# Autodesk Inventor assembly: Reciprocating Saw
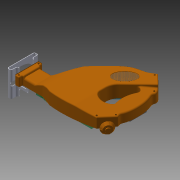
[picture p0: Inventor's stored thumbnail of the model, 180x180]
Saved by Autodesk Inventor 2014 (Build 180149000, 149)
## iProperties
Created: 2008-06
Part Number: Reciprocating Saw
Document SubType Name: Assembly
Designer: tangg
Mass: 711.371 g
Surface Area: 3987.93 cm^2
Volume: 242.811 cm^3
Density: 2.92973 g/cm^3
Author: tangg
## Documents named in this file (11)
- C:\Users\iTools\Desktop\tutorial files\Dynamic Simulation 1 and 2\Reciprocating Saw.iam
- C:\Users\iTools\Desktop\tutorial files\Dynamic Simulation 1 and 2\Saw layout.ipt
- C:\Users\iTools\Desktop\tutorial files\Dynamic Simulation 1 and 2\Guide.ipt
- C:\Users\iTools\Desktop\tutorial files\Dynamic Simulation 1 and 2\Motor housing.ipt
- C:\Users\iTools\Desktop\tutorial files\Dynamic Simulation 1 and 2\Case.ipt
- C:\Users\iTools\Desktop\tutorial files\Dynamic Simulation 1 and 2\Follower.ipt
- C:\Users\iTools\Desktop\tutorial files\Dynamic Simulation 1 and 2\Fence.ipt
- C:\Users\iTools\Desktop\tutorial files\Dynamic Simulation 1 and 2\Cam crank.iam
- C:\Users\iTools\Desktop\tutorial files\Dynamic Simulation 1 and 2\Motor.iam
- C:\Users\iTools\Desktop\tutorial files\Dynamic Simulation 1 and 2\Follower Roller.ipt
- C:\Users\iTools\Desktop\tutorial files\Dynamic Simulation 1 and 2\SKFRLS 4 A-2ZANSI.ipt
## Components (11 placed, 10 different names)
1. Saw layout:1 — Flush:15, Mate:66, Mate:76, Mate:77
2. Case:1 — Flush:16, Mate:74, Flush:19, Flush:20
3. Fence:1 — Flush:16, Mate:74
4. Guide:1 — Flush:15, Mate:71, Mate:72
5. SKF Series RLS- with Two Shields RLS 4 A-2Z:1 — Flush:19
6. SKF Series RLS- with Two Shields RLS 4 A-2Z:2 — Flush:20
7. Motor housing:1 — Mate:66, Mate:73
8. Cam crank:1 [sub-assembly] — Mate:76, Mate:77
9. Motor:1 [sub-assembly] — Mate:73
10. Follower:1 — Mate:71, Mate:72, Mate:75, Flush:17
11. Follower Roller:1 — Mate:75, Flush:17
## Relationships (13: Mate 8, Flush 5)
- Flush:15: Saw layout:1 ↔ Guide:1
- Flush:16: Case:1 ↔ Fence:1
- Mate:66: Saw layout:1 ↔ Motor housing:1
- Mate:71: Guide:1 ↔ Follower:1
- Mate:72: Guide:1 ↔ Follower:1
- Mate:73: Motor housing:1 ↔ Motor:1
- Mate:74: Case:1 ↔ Fence:1
- Mate:75: Follower:1 ↔ Follower Roller:1
- Flush:17: Follower:1 ↔ Follower Roller:1
- Mate:76: Saw layout:1 ↔ Cam crank:1
- Mate:77: Saw layout:1 ↔ Cam crank:1
- Flush:19: Case:1 ↔ SKF Series RLS- with Two Shields RLS 4 A-2Z:1
- Flush:20: Case:1 ↔ SKF Series RLS- with Two Shields RLS 4 A-2Z:2
